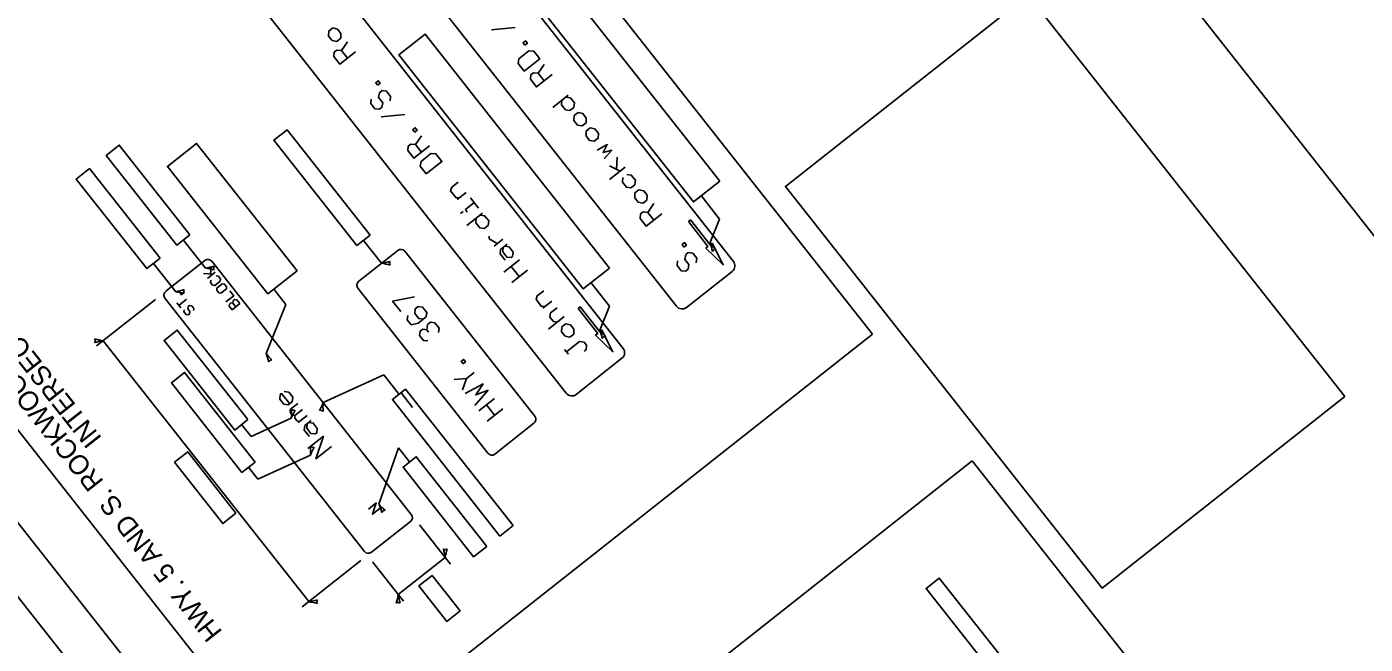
# Model space of a CAD drawing. Extents: x 671946 to 673995, y 1673066 to 1674936.
# Drawn here: x 672850 to 673404, y 1674146 to 1674401 of the extents above; entities that cross this region are included whole.
import ezdxf

# ---------------------------------------------------------------- set-up
doc = ezdxf.new("R2010")
doc.units = 0
for name, color, linetype in [('61', 7, 'Continuous'), ('C-ANNO-SYMB', 7, 'Continuous'), ('Default', 7, 'Continuous'), ('G-ANNO-TTLB', 7, 'Continuous'), ('R_Border', 7, 'Continuous'), ('T_Drafting', 7, 'Continuous')]:
    doc.layers.add(name, color=color, linetype=linetype)

msp = doc.modelspace()

# ---------------------------------------------------------------- linework, layer by layer
at = {"layer": '61'}
msp.add_lwpolyline([(673395.27, 1674248.13), (673264.23, 1674414.35), (673163.73, 1674335.12), (673294.78, 1674168.9)], close=True, dxfattribs=at)
at = {"layer": 'C-ANNO-SYMB'}
for points in [[(672961.54, 1674300.16), (672919.95, 1674352.91), (672907.85, 1674343.37), (672949.43, 1674290.62)], [(673106.47, 1673865.45), (672830.78, 1674215.15), (672815.79, 1674203.33), (673091.48, 1673853.63)]]:
    msp.add_lwpolyline(points, close=True, dxfattribs=at)
at = {"layer": 'Default'}
for points in [[(673136.5, 1674337.25), (673060.19, 1674434.05), (673049.29, 1674425.45), (673125.6, 1674328.65)], [(673090.87, 1674301.27), (673014.56, 1674398.07), (673003.65, 1674389.48), (673079.97, 1674292.68)], [(672991.77, 1674314.93), (672957.38, 1674358.56), (672951.93, 1674354.26), (672986.32, 1674310.63)], [(672917.14, 1674315.1), (672887.91, 1674352.18), (672882.46, 1674347.88), (672911.69, 1674310.8)], [(672904.8, 1674305.37), (672875.56, 1674342.45), (672870.11, 1674338.15), (672899.34, 1674301.07)], [(672941.17, 1674238.6), (672911.93, 1674275.69), (672906.48, 1674271.39), (672935.72, 1674234.31)], [(672944.16, 1674221.05), (672914.93, 1674258.13), (672909.47, 1674253.83), (672938.71, 1674216.75)], [(673050.97, 1674194.76), (673006.47, 1674251.21), (673001.02, 1674246.91), (673045.52, 1674190.46)], [(672936.24, 1674199.89), (672916.24, 1674225.25), (672910.79, 1674220.96), (672930.78, 1674195.59)], [(673040.07, 1674186.17), (673010.83, 1674223.25), (673005.38, 1674218.95), (673034.61, 1674181.87)], [(673029, 1674159.45), (673017.39, 1674174.17), (673011.94, 1674169.88), (673023.55, 1674155.15)], [(673261.79, 1674129.42), (673227.4, 1674173.05), (673221.95, 1674168.75), (673256.34, 1674125.13)]]:
    msp.add_lwpolyline(points, close=True, dxfattribs=at)
at = {"layer": 'G-ANNO-TTLB'}
msp.add_lwpolyline([(673177.78, 1673539.85), (672546.3, 1674340.87), (673064.6, 1674749.47), (673696.09, 1673948.45)], close=True, dxfattribs=at)
at = {"layer": 'T_Drafting'}
for p, q in [((673199.76, 1674273.91), (672947.99, 1674593.27)), ((673142.15, 1674304.05), (672981.61, 1674507.7)), ((672958.08, 1674489.15), (673118.62, 1674285.5)), ((673096.52, 1674268.08), (672935.97, 1674471.73)), ((672912.45, 1674453.18), (673072.99, 1674249.53)), ((672710.52, 1674406.05), (672962.28, 1674086.7)), ((673051.78, 1674400.79), (673041.97, 1674399.92)), ((672979.91, 1674391.28), (672982.41, 1674388.11)), ((673061.3, 1674381.9), (673063.79, 1674378.74)), ((673067.34, 1674367.73), (673073.82, 1674372.84)), ((673006.15, 1674364.82), (672996.34, 1674363.94)), ((673010.56, 1674352.41), (673013.05, 1674349.24)), ((673095.25, 1674341.35), (673090.86, 1674343.67)), ((673097.34, 1674343), (673090.87, 1674337.89)), ((673093.82, 1674342.12), (673094.01, 1674347.23)), ((673031.53, 1674332.63), (673027.85, 1674329.73)), ((673128.75, 1674331.31), (673136.44, 1674321.55)), ((673036.63, 1674326.15), (673033.3, 1674330.38)), ((673030.22, 1674324.74), (673029.2, 1674323.93)), ((673031.84, 1674318.9), (673038.32, 1674324.01)), ((673106.7, 1674324.31), (673109.19, 1674321.15)), ((673136.44, 1674321.55), (673132.43, 1674311.66)), ((672914.41, 1674312.95), (672923.63, 1674301.26)), ((673003.24, 1674308.61), (672987.04, 1674295.84)), ((672989.05, 1674312.78), (672996.51, 1674303.31)), ((673046.77, 1674313.3), (673043.09, 1674310.4)), ((672902.07, 1674303.22), (672911.29, 1674291.53)), ((672923.36, 1674304.46), (672907.17, 1674291.69)), ((673008.82, 1674199.39), (672926.26, 1674304.12)), ((673059.95, 1674240.01), (673006.13, 1674308.27)), ((673053.56, 1674304.68), (673047.08, 1674299.57)), ((672926.6, 1674298.74), (672922.74, 1674299.13)), ((672924.41, 1674297.01), (672927.64, 1674299.56)), ((672925.66, 1674298.83), (672925.98, 1674301.68)), ((673050.2, 1674302.02), (673053.53, 1674297.79)), ((673056.9, 1674300.44), (673050.42, 1674295.33)), ((673122.72, 1674285.02), (673141.67, 1674299.95)), ((672952.03, 1674292.5), (672956.91, 1674286.31)), ((673040.51, 1674224.69), (672986.7, 1674292.95)), ((673083.12, 1674295.33), (673090.81, 1674285.58)), ((672878.55, 1674269.14), (672902.85, 1674288.29)), ((672989.39, 1674184.07), (672906.82, 1674288.8)), ((672913.4, 1674284.8), (672911.71, 1674286.94)), ((672912.55, 1674285.87), (672915.79, 1674288.42)), ((672936.2, 1674285.3), (672934.99, 1674286.83)), ((673066.95, 1674287.69), (673063.28, 1674284.79)), ((672956.91, 1674286.31), (672948.67, 1674265.97)), ((673072.06, 1674281.21), (673065.58, 1674276.1)), ((673090.81, 1674285.58), (673086.8, 1674275.69)), ((673015.23, 1674275.81), (673015.99, 1674274.84)), ((672966.37, 1674163.3), (672881.25, 1674271.27)), ((672962.28, 1674086.7), (673199.76, 1674273.91)), ((673073.83, 1674265.65), (673072.22, 1674267.69)), ((673077.09, 1674249.04), (673096.04, 1674263.98)), ((672997.38, 1674257.13), (672972.33, 1674245.67)), ((672997.38, 1674257.13), (673003.74, 1674249.06)), ((673031.62, 1674255.65), (673034.78, 1674258.14)), ((673004.73, 1674249.51), (673009.34, 1674243.66)), ((672960.57, 1674240.32), (672963.73, 1674242.81)), ((673043.31, 1674247.33), (673036.83, 1674242.22)), ((673039.94, 1674244.68), (673043.28, 1674240.44)), ((673046.65, 1674243.1), (673040.17, 1674237.99)), ((672938.58, 1674236.57), (672942.47, 1674231.63)), ((672942.47, 1674231.63), (672959.14, 1674239.25)), ((672965.66, 1674240.36), (672961.99, 1674237.47)), ((673059.6, 1674237.11), (673043.41, 1674224.34)), ((673003.5, 1674226.94), (672995.36, 1674203.64)), ((673003.5, 1674226.94), (673008.11, 1674221.1)), ((672945.3, 1674213.99), (672967.05, 1674223.93)), ((673241.05, 1674221.53), (673003.58, 1674034.32)), ((673426.78, 1673985.94), (673241.05, 1674221.53)), ((672941.43, 1674218.9), (672945.3, 1674213.99)), ((673008.48, 1674196.49), (672992.29, 1674183.72)), ((673025, 1674178.87), (673012.23, 1674195.07)), ((673003.43, 1674166.25), (673022.87, 1674181.57)), ((672963.67, 1674161.17), (672987.97, 1674180.32)), ((673005.56, 1674163.55), (672992.79, 1674179.75))]:
    msp.add_line(p, q, dxfattribs=at)
for points in [[(672976.02, 1674395.48), (672974.57, 1674397.32), (672974.63, 1674399.35), (672976.26, 1674400.64), (672978.24, 1674400.22), (672979.69, 1674398.38), (672979.6, 1674396.4), (672977.96, 1674395.12), (672976.02, 1674395.48)], [(672985.72, 1674390.73), (672979.24, 1674385.62), (672976.75, 1674388.78), (672976.93, 1674390.66), (672978, 1674391.5), (672979.91, 1674391.28), (672982.39, 1674394.96)], [(673055.87, 1674393.51), (673055.07, 1674394.53), (673056.09, 1674395.33), (673056.89, 1674394.31), (673055.87, 1674393.51)], [(673055.52, 1674382.73), (673053.03, 1674385.89), (673053.35, 1674387.88), (673057.49, 1674391.14), (673059.5, 1674391), (673062, 1674387.83), (673055.52, 1674382.73)], [(673067.1, 1674381.35), (673060.63, 1674376.25), (673058.13, 1674379.41), (673058.31, 1674381.29), (673059.38, 1674382.13), (673061.3, 1674381.9), (673063.77, 1674385.59)], [(672994.92, 1674376.97), (672994.11, 1674377.99), (672995.13, 1674378.79), (672995.94, 1674377.77), (672994.92, 1674376.97)], [(673000.02, 1674370.49), (673000.24, 1674372.31), (672998.55, 1674374.46), (672996.69, 1674374.72), (672995.62, 1674373.88), (672995.29, 1674371.88), (672996.98, 1674369.74), (672996.66, 1674367.84), (672995.59, 1674366.99), (672993.76, 1674367.21), (672992.07, 1674369.35), (672992.25, 1674371.22)], [(673072.8, 1674372.03), (673074.66, 1674371.76), (673076.35, 1674369.62), (673076.14, 1674367.8), (673074.51, 1674366.51), (673072.68, 1674366.73), (673070.99, 1674368.87), (673071.17, 1674370.74)], [(673077.59, 1674360.5), (673076.14, 1674362.34), (673076.19, 1674364.37), (673077.83, 1674365.66), (673079.81, 1674365.24), (673081.26, 1674363.4), (673081.16, 1674361.42), (673079.53, 1674360.13), (673077.59, 1674360.5)], [(673010.24, 1674357.53), (673009.43, 1674358.55), (673010.45, 1674359.36), (673011.26, 1674358.34), (673010.24, 1674357.53)], [(673082.61, 1674354.13), (673081.17, 1674355.96), (673081.22, 1674357.99), (673082.85, 1674359.28), (673084.84, 1674358.86), (673086.29, 1674357.02), (673086.19, 1674355.05), (673084.56, 1674353.76), (673082.61, 1674354.13)], [(673016.37, 1674351.86), (673009.89, 1674346.75), (673007.39, 1674349.91), (673007.57, 1674351.79), (673008.64, 1674352.63), (673010.56, 1674352.41), (673013.03, 1674356.09)], [(673014.99, 1674340.27), (673012.5, 1674343.44), (673012.83, 1674345.43), (673016.96, 1674348.69), (673018.98, 1674348.54), (673021.47, 1674345.38), (673014.99, 1674340.27)], [(673088.65, 1674346.48), (673091.8, 1674350.03), (673088.22, 1674349.12), (673089.95, 1674352.38), (673085.75, 1674350.15)], [(673028.87, 1674330.54), (673027.33, 1674330.4), (673025.08, 1674333.25), (673025.54, 1674334.77), (673028.19, 1674336.86)], [(673098.01, 1674340.05), (673099.88, 1674339.78), (673101.57, 1674337.64), (673101.35, 1674335.81), (673099.72, 1674334.53), (673097.89, 1674334.74), (673096.21, 1674336.89), (673096.38, 1674338.76)], [(673102.8, 1674328.52), (673101.35, 1674330.36), (673101.41, 1674332.39), (673103.04, 1674333.67), (673105.03, 1674333.25), (673106.47, 1674331.42), (673106.38, 1674329.44), (673104.75, 1674328.15), (673102.8, 1674328.52)], [(673032, 1674324.48), (673031.19, 1674325.5), (673034.86, 1674328.39)], [(673112.51, 1674323.76), (673106.03, 1674318.66), (673103.53, 1674321.82), (673103.71, 1674323.7), (673104.78, 1674324.54), (673106.7, 1674324.31), (673109.17, 1674328)], [(673037.3, 1674323.2), (673039.17, 1674322.94), (673040.86, 1674320.79), (673040.64, 1674318.97), (673039.01, 1674317.68), (673037.18, 1674317.9), (673035.49, 1674320.04), (673035.67, 1674321.92)], [(673044.42, 1674311.45), (673041.01, 1674313.47), (673041.04, 1674314.57)], [(673047.72, 1674304.53), (673045.63, 1674307.19), (673045.8, 1674309.06), (673048.46, 1674311.15)], [(673047.44, 1674310.35), (673049.3, 1674310.08), (673050.99, 1674307.94), (673050.77, 1674306.12), (673050.21, 1674305.67), (673048.34, 1674305.85), (673046.65, 1674307.99), (673046.87, 1674309.91)], [(673121.7, 1674310), (673120.89, 1674311.02), (673121.92, 1674311.83), (673122.72, 1674310.81), (673121.7, 1674310)], [(673126.81, 1674303.53), (673127.02, 1674305.35), (673125.33, 1674307.49), (673123.47, 1674307.76), (673122.4, 1674306.92), (673122.07, 1674304.92), (673123.76, 1674302.78), (673123.44, 1674300.87), (673122.37, 1674300.03), (673120.54, 1674300.24), (673118.86, 1674302.39), (673119.03, 1674304.26)], [(672928.02, 1674298.04), (672928.95, 1674297.9), (672929.8, 1674296.83), (672929.69, 1674295.92), (672927.47, 1674294.17), (672926.56, 1674294.28), (672925.71, 1674295.35), (672925.8, 1674296.29)], [(672929.11, 1674291.04), (672928.27, 1674292.11), (672928.35, 1674293.05), (672930.57, 1674294.8), (672931.5, 1674294.67), (672932.35, 1674293.59), (672932.24, 1674292.68), (672930.02, 1674290.93), (672929.11, 1674291.04)], [(672933.64, 1674291.96), (672935.3, 1674289.84), (672932.07, 1674287.29)], [(673064.3, 1674285.6), (673062.76, 1674285.46), (673060.51, 1674288.31), (673060.96, 1674289.83), (673063.62, 1674291.92)], [(672913.57, 1674290.19), (672913.17, 1674290.7), (672913.68, 1674291.1), (672914.08, 1674290.59), (672913.57, 1674290.19)], [(672937.86, 1674286.61), (672934.62, 1674284.05), (672933.41, 1674285.58), (672933.56, 1674286.44), (672934.1, 1674286.87), (672934.99, 1674286.83), (672935.12, 1674287.88), (672935.71, 1674288.34), (672936.65, 1674288.14), (672937.86, 1674286.61)], [(673004.42, 1674283.34), (673001.08, 1674287.57), (673010.09, 1674289.46)], [(672918.68, 1674283.71), (672918.79, 1674284.62), (672917.94, 1674285.69), (672917.01, 1674285.82), (672916.48, 1674285.4), (672916.31, 1674284.4), (672917.16, 1674283.33), (672917, 1674282.38), (672916.46, 1674281.96), (672915.55, 1674282.07), (672914.71, 1674283.14), (672914.79, 1674284.08)], [(673007.33, 1674281.74), (673007.15, 1674279.87), (673008.72, 1674277.88), (673011.62, 1674278.51), (673014.98, 1674281.16), (673015.2, 1674282.99), (673013.51, 1674285.13), (673011.65, 1674285.4), (673010.47, 1674284.47), (673010.25, 1674282.55), (673011.93, 1674280.41), (673013.81, 1674280.24)], [(673069.15, 1674278.92), (673067.66, 1674279.23), (673066.22, 1674281.07), (673066.51, 1674282.79), (673069.17, 1674284.88)], [(673015.65, 1674271.19), (673013.83, 1674271.4), (673012.22, 1674273.44), (673012.48, 1674275.21), (673013.55, 1674276.06), (673015.23, 1674275.81), (673015.53, 1674277.95), (673016.75, 1674278.92), (673018.62, 1674278.65), (673020.31, 1674276.51), (673020.09, 1674274.68)], [(673072.49, 1674273.11), (673071.04, 1674274.95), (673071.1, 1674276.98), (673072.73, 1674278.26), (673074.72, 1674277.84), (673076.16, 1674276.01), (673076.07, 1674274.03), (673074.44, 1674272.74), (673072.49, 1674273.11)], [(673073.02, 1674266.67), (673078.48, 1674270.97), (673080.34, 1674270.7), (673081.39, 1674269.38), (673081.17, 1674267.55), (673080.36, 1674266.91)], [(673030.3, 1674261.73), (673029.5, 1674262.75), (673030.52, 1674263.55), (673031.32, 1674262.53), (673030.3, 1674261.73)], [(673026.62, 1674255.18), (673031.62, 1674255.65), (673029.95, 1674250.95)], [(673031.12, 1674249.47), (673038.52, 1674253.4), (673035.49, 1674248.86), (673040.61, 1674250.75), (673035.06, 1674244.47)], [(672956.19, 1674250.27), (672958.06, 1674250), (672959.75, 1674247.86), (672959.53, 1674246.03), (672957.9, 1674244.75), (672956.08, 1674244.96), (672954.39, 1674247.11), (672954.56, 1674248.98), (672955.12, 1674249.42), (672958.46, 1674245.19)], [(672962.5, 1674237.87), (672961.46, 1674238.13), (672960.54, 1674239.3), (672960.57, 1674240.32), (672959.61, 1674240.47), (672958.61, 1674241.75), (672958.64, 1674242.76), (672961.8, 1674245.26)], [(672966.61, 1674231.6), (672964.52, 1674234.25), (672964.7, 1674236.13), (672967.35, 1674238.22)], [(672966.33, 1674237.41), (672968.19, 1674237.15), (672969.88, 1674235), (672969.67, 1674233.18), (672969.1, 1674232.74), (672967.23, 1674232.91), (672965.54, 1674235.06), (672965.77, 1674236.97)], [(672975.79, 1674227.51), (672969.32, 1674222.4), (672972.46, 1674231.74), (672965.98, 1674226.63)], [(672995.99, 1674202.03), (672992.75, 1674199.48), (672994.32, 1674204.15), (672991.08, 1674201.59)]]:
    msp.add_lwpolyline(points, dxfattribs=at)
for points in [[(673123.51, 1674320.56), (673131.63, 1674310.25), (673130.77, 1674309.57), (673137.93, 1674302.69), (673133.35, 1674311.6), (673132.49, 1674310.93), (673124.36, 1674321.23)], [(673077.87, 1674284.58), (673086, 1674274.28), (673085.14, 1674273.6), (673092.3, 1674266.71), (673087.72, 1674275.63), (673086.86, 1674274.95), (673078.73, 1674285.26)]]:
    msp.add_lwpolyline(points, close=True, dxfattribs=at)
for centre, radius, start, end in [((673004.51, 1674306.99), 2.06, 38.2505, 128.2505), ((673153.47, 1674328.42), 26.9, 218.5447, 226.2828), ((673107.38, 1674301.88), 26.9, 13.59, 21.3281), ((673134.83, 1674307.5), 1.49, 88.0891, 151.7837), ((672924.64, 1674302.84), 2.06, 38.2505, 128.2505), ((672992.61, 1674329.92), 26.9, 278.3549, 286.093), ((672992.37, 1674276.74), 26.9, 73.4002, 81.1383), ((673001.32, 1674303.29), 1.49, 147.8993, 211.5939), ((673139.86, 1674302.25), 2.92, 308.2505, 38.2505), ((672918.95, 1674327.74), 26.9, 280.0336, 287.7717), ((672920.27, 1674274.57), 26.9, 75.0789, 82.817), ((672928.44, 1674301.38), 1.49, 149.578, 213.2726), ((672906.6, 1674318.01), 26.9, 280.0336, 287.7717), ((672916.09, 1674291.65), 1.49, 149.578, 213.2726), ((672988.32, 1674294.22), 2.06, 128.2505, 218.2505), ((672908.44, 1674290.07), 2.06, 128.2505, 218.2505), ((672907.92, 1674264.84), 26.9, 75.0789, 82.817), ((673120.91, 1674287.31), 2.92, 218.2505, 308.2505), ((673107.84, 1674292.45), 26.9, 218.5447, 226.2828), ((673061.75, 1674265.91), 26.9, 13.59, 21.3281), ((672876.45, 1674271.22), 1.49, 328.6568, 32.3514), ((672885.05, 1674297.89), 26.9, 254.1577, 261.8958), ((672885.51, 1674244.71), 26.9, 99.1124, 106.8505), ((673089.2, 1674271.52), 1.49, 88.0891, 151.7837), ((672969.67, 1674282.77), 26.9, 218.6569, 226.395), ((672923.63, 1674256.14), 26.9, 13.7021, 21.4403), ((673094.23, 1674266.27), 2.92, 308.2505, 38.2505), ((672951.07, 1674261.81), 1.49, 88.2013, 151.8959), ((673075.28, 1674251.33), 2.92, 218.2505, 308.2505), ((672932.31, 1674241.14), 26.9, 355.9712, 3.7093), ((672984.21, 1674229.5), 26.9, 151.0165, 158.7546), ((672960.19, 1674243.94), 1.49, 225.5156, 289.2102), ((672947.33, 1674255.58), 26.9, 330.653, 338.3911), ((672971.25, 1674240.99), 1.49, 45.1521, 108.8468), ((672999.15, 1674243.61), 26.9, 175.6078, 183.3459), ((673058.33, 1674238.73), 2.06, 308.2505, 38.2505), ((672940.22, 1674225.82), 26.9, 355.9712, 3.7093), ((672992.12, 1674214.18), 26.9, 151.0165, 158.7546), ((672968.11, 1674228.62), 1.49, 225.5156, 289.2102), ((673042.13, 1674225.96), 2.06, 218.2505, 308.2505), ((673015.52, 1674221.46), 26.9, 221.4771, 229.2152), ((672970.84, 1674192.59), 26.9, 16.5224, 24.2605), ((672997.97, 1674199.61), 1.49, 91.0215, 154.7161), ((673007.2, 1674198.11), 2.06, 308.2505, 38.2505), ((672991.01, 1674185.34), 2.06, 218.2505, 308.2505), ((673022.86, 1674186.38), 1.49, 238.2675, 301.9621), ((672996.28, 1674177.49), 26.9, 8.7231, 16.4612), ((673049.47, 1674177.6), 26.9, 163.7683, 171.5065), ((672976.88, 1674170.56), 26.9, 343.0462, 350.7843), ((673030.07, 1674170), 26.9, 188.0009, 195.7391), ((672962.33, 1674189.89), 26.9, 278.6398, 286.3779), ((672962.36, 1674136.7), 26.9, 73.685, 81.4231), ((672971.18, 1674163.3), 1.49, 148.1841, 211.8788), ((673003.38, 1674161.45), 1.49, 57.5453, 121.2399)]:
    msp.add_arc(centre, radius, start, end, dxfattribs=at)

# ---------------------------------------------------------------- texts
at = {"layer": 'R_Border'}
for s, p in [('HWY. 5 AND S. ROCKWOOD RD./JOHN HARDIN DR.', (672930.84, 1674150.79)), ('INTERSECTION', (672881.04, 1674230.94))]:
    msp.add_text(s, height=8.082, rotation=128.2505, dxfattribs=at).set_placement(p)

doc.saveas('drawing.dxf')
